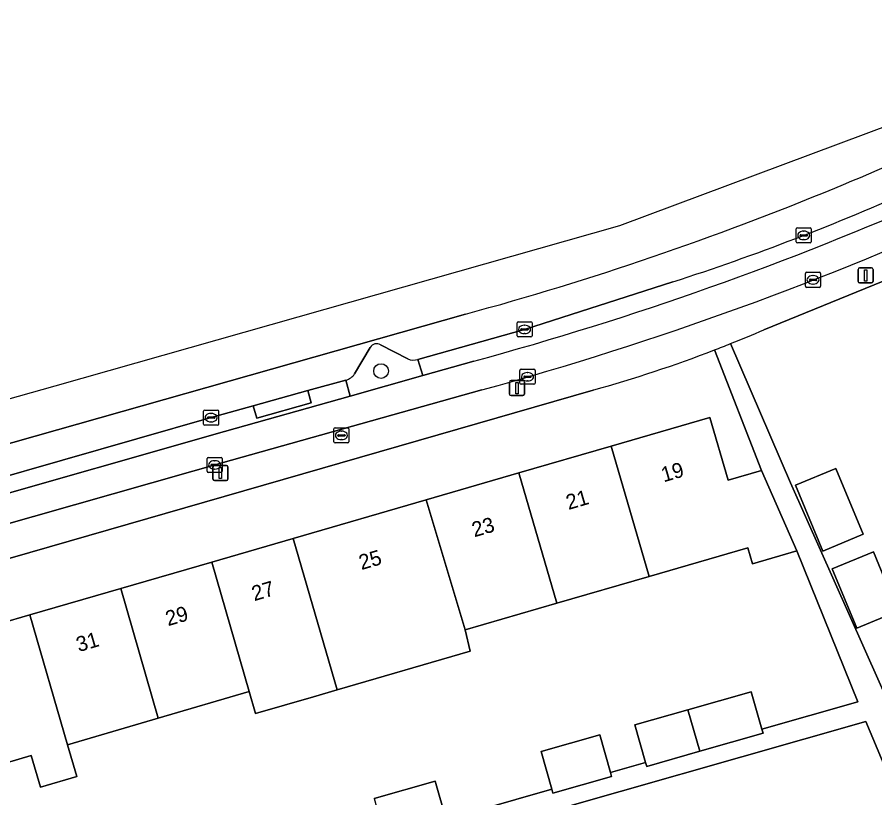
# Model space of a CAD drawing. Extents: x 162073 to 163043, y 381818 to 382561.
# Drawn here: x 162242.9 to 162299.9, y 382459.5 to 382511.3 of the extents above; entities that cross this region are included whole.
import ezdxf

# ---------------------------------------------------------------- set-up
doc = ezdxf.new("R2010")
doc.units = 0
for name, color, linetype in [('IMGEO_Berm_groen', 7, 'Continuous'), ('IMGEO_Berm_open', 7, 'Continuous'), ('IMGEO_Boom', 7, 'Continuous'), ('IMGEO_Brandkraan', 7, 'Continuous'), ('IMGEO_Erf', 7, 'Continuous'), ('IMGEO_Fietspad_open', 7, 'Continuous'), ('IMGEO_Groenvoorziening', 7, 'Continuous'), ('IMGEO_Kolk', 7, 'Continuous'), ('IMGEO_Lichtmast', 7, 'Continuous'), ('IMGEO_Pand', 7, 'Continuous'), ('IMGEO_Pand_nummerreeks', 7, 'Continuous'), ('IMGEO_Parkeervlak_open', 7, 'Continuous'), ('IMGEO_Rijbaan_lokaal_gesloten', 7, 'Continuous'), ('IMGEO_Voetpad_open', 7, 'Continuous')]:
    doc.layers.add(name, color=color, linetype=linetype)

msp = doc.modelspace()

# ---------------------------------------------------------------- linework, layer by layer
at = {"layer": 'IMGEO_Berm_groen'}
for points in [[(162268.826, 382488.65), (162267.017, 382489.588)], [(162266.336, 382489.408), (162265.295, 382487.652)], [(162264.719, 382487.231), (162265.001, 382486.183), (162269.839, 382487.545), (162269.509, 382488.619)]]:
    msp.add_lwpolyline(points, dxfattribs=at)
for centre, radius, start, end in [((162266.761, 382489.177), 0.484, 58.1556, 151.4557), ((162269.211, 382489.591), 1.016, 247.7441, 287.0584), ((162264.363, 382488.322), 1.148, 288.0577, 324.2687)]:
    msp.add_arc(centre, radius, start, end, dxfattribs=at)
at = {"layer": 'IMGEO_Berm_open'}
msp.add_lwpolyline([(162286.431, 382493.761), (162276.59, 382490.612), (162269.509, 382488.619), (162269.839, 382487.545), (162273.231, 382488.5)], dxfattribs=at)
for points in [[(162256.653, 382483.833), (162265.001, 382486.183), (162264.719, 382487.231), (162262.184, 382486.558), (162262.414, 382485.743), (162258.799, 382484.707), (162258.567, 382485.54), (162255.768, 382484.752), (162235.989, 382479.101), (162229.186, 382477.182), (162229.321, 382476.701), (162222.939, 382474.911), (162222.814, 382475.355), (162222.174, 382475.171), (162222.483, 382474.099)], [(162262.184, 382486.558), (162258.567, 382485.54), (162258.799, 382484.707), (162262.414, 382485.743)]]:
    msp.add_lwpolyline(points, close=True, dxfattribs=at)
for centre, radius, start, end in [((162238.249, 382643.061), 156.882, 287.88577, 294.23047), ((162215.173, 382701.195), 220.476, 285.26768, 293.80585)]:
    msp.add_arc(centre, radius, start, end, dxfattribs=at)
at = {"layer": 'IMGEO_Boom'}
msp.add_circle((162267.061, 382487.844), 0.489, dxfattribs=at)
at = {"layer": 'IMGEO_Brandkraan'}
for p, q in [((162263.926, 382483.147), (162263.926, 382483.999)), ((162264.001, 382484.073), (162264.853, 382484.073)), ((162264.414, 382483.853), (162264.439, 382483.853)), ((162264.927, 382483.999), (162264.927, 382483.147)), ((162264.185, 382483.567), (162264.185, 382483.579)), ((162264.623, 382483.53), (162264.225, 382483.53)), ((162264.228, 382483.616), (162264.626, 382483.616)), ((162264.437, 382483.293), (162264.412, 382483.293)), ((162264.669, 382483.579), (162264.669, 382483.567)), ((162264.853, 382483.073), (162264.001, 382483.073))]:
    msp.add_line(p, q, dxfattribs=at)
for points in [[(162263.926, 382483.147), (162263.926, 382483.999)], [(162264.001, 382484.073), (162264.853, 382484.073)], [(162264.927, 382483.999), (162264.927, 382483.147)], [(162264.853, 382483.073), (162264.001, 382483.073)]]:
    msp.add_lwpolyline(points, dxfattribs=at)
for centre, radius, start, end in [((162264.003, 382483.997), 0.0765, 91.552, 178.448), ((162264.003, 382483.997), 0.0765, 91.552, 178.448), ((162264.851, 382483.997), 0.0765, 1.552, 88.448), ((162264.851, 382483.997), 0.0765, 1.552, 88.448), ((162264.225, 382483.576), 0.0403, 85.8775, 175.7526), ((162264.222, 382483.566), 0.0366, 178.938, 274.7102), ((162264.626, 382483.573), 0.043, 264.8664, 352.4533), ((162264.63, 382483.578), 0.0386, 1.7309, 96.639), ((162264.003, 382483.149), 0.0765, 181.552, 268.448), ((162264.003, 382483.149), 0.0765, 181.552, 268.448), ((162264.851, 382483.149), 0.0765, 271.552, 358.448), ((162264.851, 382483.149), 0.0765, 271.552, 358.448)]:
    msp.add_arc(centre, radius, start, end, dxfattribs=at)
for centre, major_axis, ratio, start_param, end_param in [((162264.413, 382483.573), (-0.387, 0.002), 0.722429, 4.712389, 7.853982), ((162264.438, 382483.573), (-0.39, 0.002), 0.717154, 1.570796, 4.712389)]:
    msp.add_ellipse(centre, major_axis=major_axis, ratio=ratio, start_param=start_param, end_param=end_param, dxfattribs=at)
at = {"layer": 'IMGEO_Erf'}
for points in [[(162313.104, 382499.207), (162306.559, 382496.312), (162292.494, 382490.583)], [(162290.282, 382489.666), (162294.266, 382480.427), (162303.05, 382460.692)], [(162276.217, 382481.076), (162282.349, 382482.856), (162288.903, 382484.758), (162290.113, 382480.59), (162292.322, 382481.231), (162289.219, 382489.25)], [(162281.138, 382486.577), (162210.186, 382466.143), (162196.532, 382462.029)], [(162198.731, 382452.553), (162200.106, 382452.948), (162198.53, 382458.53), (162204.342, 382460.216), (162211.24, 382462.219), (162218.089, 382464.206), (162225.039, 382466.224), (162227.194, 382466.849), (162230.087, 382467.689), (162231.71, 382468.16), (162237.782, 382469.922), (162243.726, 382471.647), (162249.76, 382473.398), (162255.807, 382475.153), (162261.214, 382476.722), (162270.049, 382479.286), (162276.217, 382481.076)], [(162266.589, 382459.454), (162270.654, 382460.61), (162271.38, 382458.06), (162278.404, 382460.066), (162277.69, 382462.576), (162281.591, 382463.685), (162282.303, 382461.18), (162284.631, 382461.845), (162283.919, 382464.348), (162287.432, 382465.347), (162291.654, 382466.549), (162292.364, 382464.054), (162298.729, 382465.872), (162294.676, 382475.897), (162293.933, 382475.68), (162291.724, 382475.039), (162291.415, 382476.102), (162284.862, 382474.2), (162278.73, 382472.42), (162272.644, 382470.654), (162272.969, 382469.233), (162264.134, 382466.668), (162262.575, 382466.216), (162258.726, 382465.1), (162258.3, 382466.566), (162252.259, 382464.789), (162246.231, 382463.016), (162246.847, 382460.923), (162244.435, 382460.213), (162243.819, 382462.306), (162240.295, 382461.27)]]:
    msp.add_lwpolyline(points, dxfattribs=at)
for points in [[(162296.413, 382475.887), (162294.597, 382480.26), (162297.28, 382481.374), (162299.096, 382477.002)], [(162298.661, 382470.762), (162297.024, 382474.703), (162299.762, 382475.841), (162301.399, 382471.899)]]:
    msp.add_lwpolyline(points, close=True, dxfattribs=at)
for centre, radius, start, end in [((162257.915, 382570.869), 87.417, 291.73204, 293.30155), ((162257.122, 382572.733), 89.441, 285.57567, 291.03027)]:
    msp.add_arc(centre, radius, start, end, dxfattribs=at)
at = {"layer": 'IMGEO_Fietspad_open'}
for points in [[(162273.231, 382488.5), (162269.839, 382487.545), (162265.001, 382486.183), (162256.653, 382483.833), (162222.483, 382474.099), (162217.656, 382472.724), (162200.318, 382467.785), (162196.229, 382466.62), (162193.304, 382465.813)], [(162257.119, 382481.925), (162273.742, 382486.587)], [(162195.807, 382464.462), (162196.777, 382464.766), (162257.119, 382481.925)]]:
    msp.add_lwpolyline(points, dxfattribs=at)
for centre, radius, start, end in [((162215.173, 382701.195), 220.476, 285.26768, 293.80585), ((162213.23, 382705.872), 227.481, 285.4269, 294.50724)]:
    msp.add_arc(centre, radius, start, end, dxfattribs=at)
at = {"layer": 'IMGEO_Groenvoorziening'}
msp.add_lwpolyline([(162306.255, 382425.322), (162315.263, 382426.443), (162311.418, 382435.613), (162299.273, 382464.574), (162274.708, 382457.582), (162275.707, 382454.072), (162272.244, 382453.087), (162271.245, 382456.597), (162244.62, 382448.751), (162238.202, 382446.863), (162235.289, 382457.183), (162234.842, 382458.721), (162234.425, 382458.6), (162232.856, 382458.145), (162229.964, 382457.305), (162228.555, 382456.896), (162231.764, 382445.146), (162227.375, 382443.919), (162204.454, 382437.432), (162205.333, 382434.403), (162201.749, 382433.363), (162212.159, 382387.115), (162219.291, 382354.42)], dxfattribs=at)
at = {"layer": 'IMGEO_Kolk'}
for p, q in [((162294.638, 382496.43), (162294.638, 382497.282)), ((162294.713, 382497.356), (162295.565, 382497.356)), ((162294.897, 382496.85), (162294.897, 382496.862)), ((162294.94, 382496.899), (162295.338, 382496.899)), ((162295.126, 382497.136), (162295.151, 382497.136)), ((162295.381, 382496.862), (162295.381, 382496.85)), ((162295.639, 382497.282), (162295.639, 382496.43)), ((162295.565, 382496.356), (162294.713, 382496.356)), ((162295.335, 382496.813), (162294.937, 382496.813)), ((162295.149, 382496.576), (162295.124, 382496.576)), ((162295.255, 382493.476), (162295.255, 382494.328)), ((162295.33, 382494.402), (162296.182, 382494.402)), ((162295.743, 382494.182), (162295.768, 382494.182)), ((162296.256, 382494.328), (162296.256, 382493.476)), ((162295.514, 382493.896), (162295.514, 382493.908)), ((162295.952, 382493.859), (162295.554, 382493.859)), ((162295.557, 382493.945), (162295.955, 382493.945)), ((162295.766, 382493.622), (162295.741, 382493.622)), ((162295.998, 382493.908), (162295.998, 382493.896)), ((162296.182, 382493.402), (162295.33, 382493.402)), ((162276.089, 382490.185), (162276.089, 382491.037)), ((162276.164, 382491.111), (162277.016, 382491.111)), ((162276.348, 382490.605), (162276.348, 382490.617)), ((162276.391, 382490.654), (162276.789, 382490.654)), ((162276.577, 382490.891), (162276.602, 382490.891)), ((162276.832, 382490.617), (162276.832, 382490.605)), ((162277.09, 382491.037), (162277.09, 382490.185)), ((162277.016, 382490.111), (162276.164, 382490.111)), ((162276.786, 382490.568), (162276.388, 382490.568)), ((162276.6, 382490.331), (162276.575, 382490.331)), ((162276.286, 382487.039), (162276.286, 382487.891)), ((162276.361, 382487.965), (162277.213, 382487.965)), ((162276.774, 382487.745), (162276.799, 382487.745)), ((162277.287, 382487.891), (162277.287, 382487.039)), ((162276.545, 382487.459), (162276.545, 382487.471)), ((162276.983, 382487.422), (162276.585, 382487.422)), ((162276.588, 382487.508), (162276.986, 382487.508)), ((162276.797, 382487.185), (162276.772, 382487.185)), ((162277.029, 382487.471), (162277.029, 382487.459)), ((162277.213, 382486.965), (162276.361, 382486.965)), ((162255.268, 382484.325), (162255.268, 382485.177)), ((162255.343, 382485.251), (162256.195, 382485.251)), ((162255.756, 382485.031), (162255.781, 382485.031)), ((162256.269, 382485.177), (162256.269, 382484.325)), ((162255.527, 382484.745), (162255.527, 382484.757)), ((162255.965, 382484.708), (162255.567, 382484.708)), ((162255.57, 382484.794), (162255.968, 382484.794)), ((162255.779, 382484.471), (162255.754, 382484.471)), ((162256.011, 382484.757), (162256.011, 382484.745)), ((162256.195, 382484.251), (162255.343, 382484.251)), ((162255.502, 382481.185), (162255.502, 382482.037)), ((162255.577, 382482.111), (162256.429, 382482.111)), ((162256.503, 382482.037), (162256.503, 382481.185)), ((162255.761, 382481.605), (162255.761, 382481.617)), ((162256.199, 382481.568), (162255.801, 382481.568)), ((162255.804, 382481.654), (162256.202, 382481.654)), ((162255.99, 382481.891), (162256.015, 382481.891)), ((162256.245, 382481.617), (162256.245, 382481.605)), ((162256.429, 382481.111), (162255.577, 382481.111)), ((162256.013, 382481.331), (162255.988, 382481.331))]:
    msp.add_line(p, q, dxfattribs=at)
for points in [[(162294.638, 382496.43), (162294.638, 382497.282)], [(162294.713, 382497.356), (162295.565, 382497.356)], [(162295.639, 382497.282), (162295.639, 382496.43)], [(162295.565, 382496.356), (162294.713, 382496.356)], [(162295.255, 382493.476), (162295.255, 382494.328)], [(162295.33, 382494.402), (162296.182, 382494.402)], [(162296.256, 382494.328), (162296.256, 382493.476)], [(162296.182, 382493.402), (162295.33, 382493.402)], [(162276.089, 382490.185), (162276.089, 382491.037)], [(162276.164, 382491.111), (162277.016, 382491.111)], [(162277.09, 382491.037), (162277.09, 382490.185)], [(162277.016, 382490.111), (162276.164, 382490.111)], [(162276.286, 382487.039), (162276.286, 382487.891)], [(162276.361, 382487.965), (162277.213, 382487.965)], [(162277.287, 382487.891), (162277.287, 382487.039)], [(162277.213, 382486.965), (162276.361, 382486.965)], [(162255.268, 382484.325), (162255.268, 382485.177)], [(162255.343, 382485.251), (162256.195, 382485.251)], [(162256.269, 382485.177), (162256.269, 382484.325)], [(162256.195, 382484.251), (162255.343, 382484.251)], [(162255.502, 382481.185), (162255.502, 382482.037)], [(162255.577, 382482.111), (162256.429, 382482.111)], [(162256.503, 382482.037), (162256.503, 382481.185)], [(162256.429, 382481.111), (162255.577, 382481.111)]]:
    msp.add_lwpolyline(points, dxfattribs=at)
for centre, radius, start, end in [((162294.715, 382497.28), 0.0765, 91.552, 178.448), ((162294.715, 382497.28), 0.0765, 91.552, 178.448), ((162294.937, 382496.859), 0.0403, 85.8775, 175.7526), ((162294.934, 382496.849), 0.0366, 178.938, 274.7102), ((162295.338, 382496.856), 0.043, 264.8664, 352.4533), ((162295.342, 382496.861), 0.0386, 1.7309, 96.639), ((162295.563, 382497.28), 0.0765, 1.552, 88.448), ((162295.563, 382497.28), 0.0765, 1.552, 88.448), ((162294.715, 382496.432), 0.0765, 181.552, 268.448), ((162294.715, 382496.432), 0.0765, 181.552, 268.448), ((162295.563, 382496.432), 0.0765, 271.552, 358.448), ((162295.563, 382496.432), 0.0765, 271.552, 358.448), ((162295.332, 382494.326), 0.0765, 91.552, 178.448), ((162295.332, 382494.326), 0.0765, 91.552, 178.448), ((162296.18, 382494.326), 0.0765, 1.552, 88.448), ((162296.18, 382494.326), 0.0765, 1.552, 88.448), ((162295.332, 382493.478), 0.0765, 181.552, 268.448), ((162295.332, 382493.478), 0.0765, 181.552, 268.448), ((162295.554, 382493.905), 0.0403, 85.8775, 175.7526), ((162295.551, 382493.895), 0.0366, 178.938, 274.7102), ((162295.955, 382493.902), 0.043, 264.8664, 352.4533), ((162295.959, 382493.907), 0.0386, 1.7309, 96.639), ((162296.18, 382493.478), 0.0765, 271.552, 358.448), ((162296.18, 382493.478), 0.0765, 271.552, 358.448), ((162276.166, 382491.035), 0.0765, 91.552, 178.448), ((162276.166, 382491.035), 0.0765, 91.552, 178.448), ((162276.388, 382490.614), 0.0403, 85.8775, 175.7526), ((162276.385, 382490.604), 0.0366, 178.938, 274.7102), ((162276.789, 382490.611), 0.043, 264.8664, 352.4533), ((162276.793, 382490.616), 0.0386, 1.7309, 96.639), ((162277.014, 382491.035), 0.0765, 1.552, 88.448), ((162277.014, 382491.035), 0.0765, 1.552, 88.448), ((162276.166, 382490.187), 0.0765, 181.552, 268.448), ((162276.166, 382490.187), 0.0765, 181.552, 268.448), ((162277.014, 382490.187), 0.0765, 271.552, 358.448), ((162277.014, 382490.187), 0.0765, 271.552, 358.448), ((162276.363, 382487.889), 0.0765, 91.552, 178.448), ((162276.363, 382487.889), 0.0765, 91.552, 178.448), ((162277.211, 382487.889), 0.0765, 1.552, 88.448), ((162277.211, 382487.889), 0.0765, 1.552, 88.448), ((162276.585, 382487.468), 0.0403, 85.8775, 175.7526), ((162276.582, 382487.458), 0.0366, 178.938, 274.7102), ((162276.986, 382487.465), 0.043, 264.8664, 352.4533), ((162276.99, 382487.47), 0.0386, 1.7309, 96.639), ((162276.363, 382487.041), 0.0765, 181.552, 268.448), ((162276.363, 382487.041), 0.0765, 181.552, 268.448), ((162277.211, 382487.041), 0.0765, 271.552, 358.448), ((162277.211, 382487.041), 0.0765, 271.552, 358.448), ((162255.345, 382485.175), 0.0765, 91.552, 178.448), ((162255.345, 382485.175), 0.0765, 91.552, 178.448), ((162256.193, 382485.175), 0.0765, 1.552, 88.448), ((162256.193, 382485.175), 0.0765, 1.552, 88.448), ((162255.345, 382484.327), 0.0765, 181.552, 268.448), ((162255.345, 382484.327), 0.0765, 181.552, 268.448), ((162255.567, 382484.754), 0.0403, 85.8775, 175.7526), ((162255.564, 382484.744), 0.0366, 178.938, 274.7102), ((162255.968, 382484.751), 0.043, 264.8664, 352.4533), ((162255.972, 382484.756), 0.0386, 1.7309, 96.639), ((162256.193, 382484.327), 0.0765, 271.552, 358.448), ((162256.193, 382484.327), 0.0765, 271.552, 358.448), ((162255.579, 382482.035), 0.0765, 91.552, 178.448), ((162255.579, 382482.035), 0.0765, 91.552, 178.448), ((162256.427, 382482.035), 0.0765, 1.552, 88.448), ((162256.427, 382482.035), 0.0765, 1.552, 88.448), ((162255.801, 382481.614), 0.0403, 85.8775, 175.7526), ((162255.798, 382481.604), 0.0366, 178.938, 274.7102), ((162256.202, 382481.611), 0.043, 264.8664, 352.4533), ((162256.206, 382481.616), 0.0386, 1.7309, 96.639), ((162255.579, 382481.187), 0.0765, 181.552, 268.448), ((162255.579, 382481.187), 0.0765, 181.552, 268.448), ((162256.427, 382481.187), 0.0765, 271.552, 358.448), ((162256.427, 382481.187), 0.0765, 271.552, 358.448)]:
    msp.add_arc(centre, radius, start, end, dxfattribs=at)
for centre, major_axis, ratio, start_param, end_param in [((162295.125, 382496.856), (-0.387, 0.002), 0.722429, 4.712389, 7.853982), ((162295.15, 382496.856), (-0.39, 0.002), 0.717154, 1.570796, 4.712389), ((162295.742, 382493.902), (-0.387, 0.002), 0.722429, 4.712389, 7.853982), ((162295.767, 382493.902), (-0.39, 0.002), 0.717154, 1.570796, 4.712389), ((162276.576, 382490.611), (-0.387, 0.002), 0.722429, 4.712389, 7.853982), ((162276.601, 382490.611), (-0.39, 0.002), 0.717154, 1.570796, 4.712389), ((162276.773, 382487.465), (-0.387, 0.002), 0.722429, 4.712389, 7.853982), ((162276.798, 382487.465), (-0.39, 0.002), 0.717154, 1.570796, 4.712389), ((162255.755, 382484.751), (-0.387, 0.002), 0.722429, 4.712389, 7.853982), ((162255.78, 382484.751), (-0.39, 0.002), 0.717154, 1.570796, 4.712389), ((162255.989, 382481.611), (-0.387, 0.002), 0.722429, 4.712389, 7.853982), ((162256.014, 382481.611), (-0.39, 0.002), 0.717154, 1.570796, 4.712389)]:
    msp.add_ellipse(centre, major_axis=major_axis, ratio=ratio, start_param=start_param, end_param=end_param, dxfattribs=at)
at = {"layer": 'IMGEO_Lichtmast'}
for p, q in [((162298.752, 382493.797), (162298.752, 382494.597)), ((162298.752, 382494.597), (162298.752, 382493.797)), ((162298.852, 382494.697), (162299.642, 382494.697)), ((162299.642, 382494.697), (162298.852, 382494.697)), ((162299.742, 382494.597), (162299.742, 382493.797)), ((162299.742, 382493.797), (162299.742, 382494.597)), ((162299.642, 382493.697), (162298.852, 382493.697)), ((162298.852, 382493.697), (162299.642, 382493.697)), ((162275.691, 382487.217), (162276.481, 382487.217)), ((162276.481, 382487.217), (162275.691, 382487.217)), ((162275.591, 382486.317), (162275.591, 382487.117)), ((162275.591, 382487.117), (162275.591, 382486.317)), ((162276.581, 382487.117), (162276.581, 382486.317)), ((162276.581, 382486.317), (162276.581, 382487.117)), ((162276.481, 382486.217), (162275.691, 382486.217)), ((162275.691, 382486.217), (162276.481, 382486.217)), ((162255.891, 382480.673), (162255.891, 382481.473)), ((162255.891, 382481.473), (162255.891, 382480.673)), ((162255.991, 382481.573), (162256.781, 382481.573)), ((162256.781, 382481.573), (162255.991, 382481.573)), ((162256.881, 382481.473), (162256.881, 382480.673)), ((162256.881, 382480.673), (162256.881, 382481.473)), ((162256.781, 382480.573), (162255.991, 382480.573)), ((162255.991, 382480.573), (162256.781, 382480.573))]:
    msp.add_line(p, q, dxfattribs=at)
for points in [[(162299.172, 382494.572), (162299.322, 382494.572), (162299.322, 382493.822), (162299.172, 382493.822), (162299.172, 382494.572)], [(162276.011, 382487.092), (162276.161, 382487.092), (162276.161, 382486.342), (162276.011, 382486.342), (162276.011, 382487.092)], [(162256.311, 382481.448), (162256.461, 382481.448), (162256.461, 382480.698), (162256.311, 382480.698), (162256.311, 382481.448)]]:
    msp.add_lwpolyline(points, dxfattribs=at)
for centre, start, end in [((162298.852, 382494.597), 90, 180), ((162298.852, 382494.597), 90, 180), ((162299.642, 382494.597), 0, 90), ((162299.642, 382494.597), 360, 90), ((162298.852, 382493.797), 180, 270), ((162298.852, 382493.797), 180, 270), ((162299.642, 382493.797), 270, 0), ((162299.642, 382493.797), 270, 0), ((162275.691, 382487.117), 90, 180), ((162275.691, 382487.117), 90, 180), ((162276.481, 382487.117), 0, 90), ((162276.481, 382487.117), 360, 90), ((162275.691, 382486.317), 180, 270), ((162275.691, 382486.317), 180, 270), ((162276.481, 382486.317), 270, 0), ((162276.481, 382486.317), 270, 0), ((162255.991, 382481.473), 90, 180), ((162255.991, 382481.473), 90, 180), ((162256.781, 382481.473), 0, 90), ((162256.781, 382481.473), 360, 90), ((162255.991, 382480.673), 180, 270), ((162255.991, 382480.673), 180, 270), ((162256.781, 382480.673), 270, 0), ((162256.781, 382480.673), 270, 0)]:
    msp.add_arc(centre, 0.1, start, end, dxfattribs=at)
at = {"layer": 'IMGEO_Pand'}
for points in [[(162292.322, 382481.231), (162290.113, 382480.59), (162288.903, 382484.758), (162282.349, 382482.856), (162284.862, 382474.2), (162291.415, 382476.102), (162291.724, 382475.039), (162293.933, 382475.68), (162294.676, 382475.897)], [(162276.217, 382481.076), (162278.73, 382472.42), (162284.862, 382474.2), (162282.349, 382482.856)], [(162270.049, 382479.286), (162272.644, 382470.654), (162278.73, 382472.42), (162276.217, 382481.076)], [(162296.413, 382475.887), (162299.096, 382477.002), (162297.28, 382481.374), (162294.597, 382480.26)], [(162270.049, 382479.286), (162261.214, 382476.722), (162264.134, 382466.668), (162272.969, 382469.233), (162272.644, 382470.654)], [(162261.214, 382476.722), (162255.807, 382475.153), (162258.3, 382466.566), (162258.726, 382465.1), (162262.575, 382466.216), (162264.134, 382466.668)], [(162301.399, 382471.899), (162299.762, 382475.841), (162297.024, 382474.703), (162298.661, 382470.762)], [(162252.259, 382464.789), (162258.3, 382466.566), (162255.807, 382475.153), (162249.76, 382473.398)], [(162252.259, 382464.789), (162249.76, 382473.398), (162243.726, 382471.647), (162246.231, 382463.016)], [(162243.726, 382471.647), (162237.782, 382469.922), (162240.295, 382461.27), (162243.819, 382462.306), (162244.435, 382460.213), (162246.847, 382460.923), (162246.231, 382463.016)], [(162287.432, 382465.347), (162288.232, 382462.591), (162292.44, 382463.788), (162292.364, 382464.054), (162291.654, 382466.549)], [(162287.432, 382465.347), (162283.919, 382464.348), (162284.631, 382461.845), (162284.704, 382461.587), (162288.232, 382462.591)], [(162278.404, 382460.066), (162278.475, 382459.815), (162282.376, 382460.924), (162282.303, 382461.18), (162281.591, 382463.685), (162277.69, 382462.576)], [(162266.589, 382459.454), (162267.316, 382456.899), (162267.357, 382456.754), (162271.422, 382457.911), (162271.38, 382458.06), (162270.654, 382460.61)]]:
    msp.add_lwpolyline(points, close=True, dxfattribs=at)
at = {"layer": 'IMGEO_Parkeervlak_open'}
for points in [[(162269.509, 382488.619), (162276.59, 382490.612), (162286.431, 382493.761)], [(162272.662, 382491.623), (162198.275, 382470.548), (162198.13, 382470.507), (162196.514, 382469.997), (162196.405, 382469.966), (162196.642, 382470.014)], [(162267.017, 382489.588), (162268.826, 382488.65)], [(162265.295, 382487.652), (162266.336, 382489.408)], [(162258.567, 382485.54), (162262.184, 382486.558), (162264.719, 382487.231)], [(162222.174, 382475.171), (162222.814, 382475.355), (162229.186, 382477.182), (162235.989, 382479.101), (162255.768, 382484.752), (162258.567, 382485.54)]]:
    msp.add_lwpolyline(points, dxfattribs=at)
for centre, radius, start, end in [((162218.23, 382691.119), 206.795, 292.45218, 295.16097), ((162218.48, 382690.525), 206.15, 285.23784, 292.45083), ((162238.249, 382643.061), 156.882, 287.88577, 294.23047), ((162266.761, 382489.177), 0.484, 58.1556, 151.4557), ((162269.211, 382489.591), 1.016, 247.7441, 287.0584), ((162264.363, 382488.322), 1.148, 288.0577, 324.2687)]:
    msp.add_arc(centre, radius, start, end, dxfattribs=at)
at = {"layer": 'IMGEO_Rijbaan_lokaal_gesloten'}
for points in [[(162315.724, 382511.35), (162306.448, 382506.279), (162282.905, 382497.501), (162245.387, 382486.842), (162201.279, 382474.422), (162185.966, 382468.979), (162180.588, 382467.067), (162160.813, 382456.745), (162145.022, 382444.832), (162130.306, 382431.424), (162118.152, 382417.002), (162108.457, 382405.716), (162072.514, 382380.58)], [(162176.456, 382462.089), (162177.565, 382462.654), (162179.019, 382463.222), (162195.861, 382469.81), (162196.405, 382469.966), (162196.514, 382469.997), (162198.13, 382470.507), (162198.275, 382470.548), (162272.662, 382491.623)]]:
    msp.add_lwpolyline(points, dxfattribs=at)
for centre, radius, start, end in [((162218.23, 382691.119), 206.795, 292.45218, 295.16097), ((162218.48, 382690.525), 206.15, 285.23784, 292.45083)]:
    msp.add_arc(centre, radius, start, end, dxfattribs=at)
at = {"layer": 'IMGEO_Voetpad_open'}
for points in [[(162292.494, 382490.583), (162306.559, 382496.312)], [(162299.273, 382464.574), (162311.418, 382435.613), (162313.211, 382436.365), (162312.839, 382437.332), (162311.244, 382441.139), (162311.433, 382441.218), (162310.931, 382442.37), (162310.758, 382442.297), (162309.176, 382446.073), (162309.345, 382446.144), (162308.887, 382447.22), (162308.724, 382447.152), (162307.126, 382450.966), (162307.32, 382451.047), (162306.862, 382452.07), (162306.693, 382451.999), (162305.119, 382455.756), (162305.452, 382455.896), (162304.964, 382457.102), (162304.616, 382456.956), (162303.05, 382460.692), (162294.266, 382480.427), (162290.282, 382489.666)], [(162289.219, 382489.25), (162292.322, 382481.231), (162294.676, 382475.897), (162298.729, 382465.872), (162292.364, 382464.054), (162292.44, 382463.788), (162288.232, 382462.591), (162284.704, 382461.587), (162284.631, 382461.845), (162282.303, 382461.18), (162282.376, 382460.924), (162278.475, 382459.815), (162278.404, 382460.066), (162271.38, 382458.06)], [(162273.742, 382486.587), (162257.119, 382481.925), (162196.777, 382464.766), (162195.807, 382464.462)], [(162196.532, 382462.029), (162210.186, 382466.143), (162281.138, 382486.577)], [(162274.708, 382457.582), (162299.273, 382464.574)]]:
    msp.add_lwpolyline(points, dxfattribs=at)
for centre, radius, start, end in [((162213.23, 382705.872), 227.481, 285.4269, 294.50724), ((162257.915, 382570.869), 87.417, 291.73204, 293.30155), ((162260.72, 382563.638), 79.661, 290.96214, 291.78317), ((162260.72, 382563.638), 79.661, 290.96214, 291.78317), ((162257.122, 382572.733), 89.441, 285.57567, 291.03027)]:
    msp.add_arc(centre, radius, start, end, dxfattribs=at)

# ---------------------------------------------------------------- texts
at = {"layer": 'IMGEO_Pand_nummerreeks'}
for s, rotation, p in [('19', 16.1861, (162285.833, 382480.452)), ('21', 16.1833, (162279.512, 382478.617)), ('23', 16.1833, (162273.254, 382476.801)), ('25', 16.1833, (162265.753, 382474.624)), ('27', 16.1861, (162258.631, 382472.558)), ('29', 16.1833, (162252.904, 382470.896)), ('31', 16.1833, (162246.972, 382469.174))]:
    msp.add_text(s, height=1, rotation=rotation, dxfattribs=at).set_placement(p)

doc.saveas('drawing.dxf')
